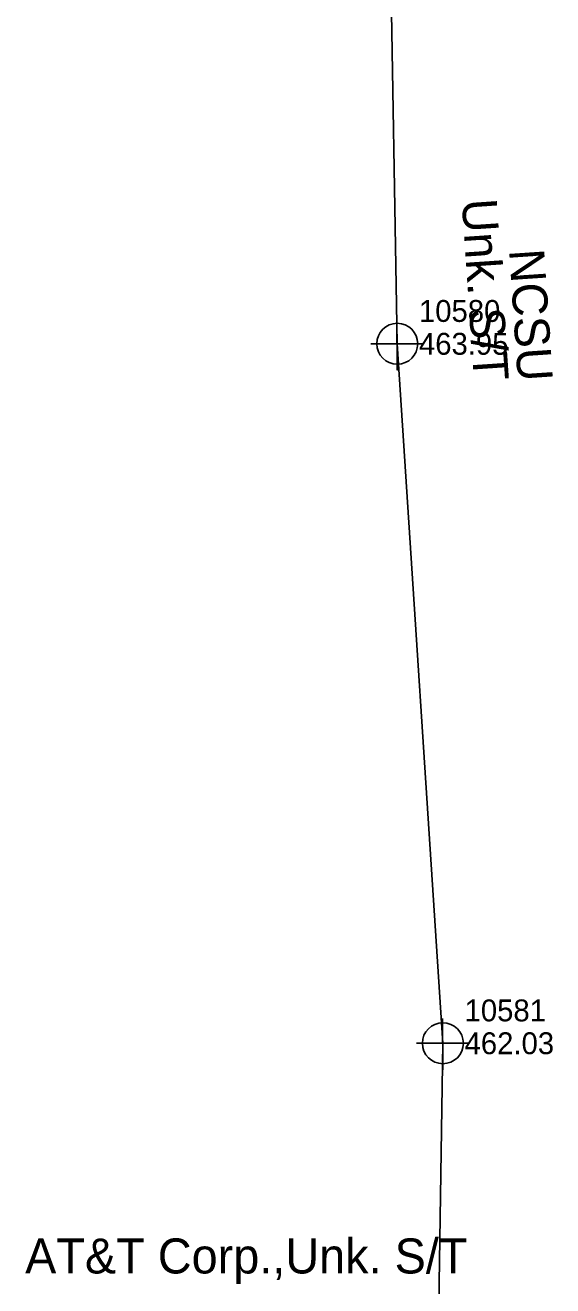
# Model space of a CAD drawing. Extents: x 2083698 to 2094313, y 743246 to 752873.
# Drawn here: x 2088906.7 to 2088967, y 744424 to 744568 of the extents above; entities that cross this region are included whole.
import ezdxf

# ---------------------------------------------------------------- set-up
doc = ezdxf.new("R2010")
doc.units = 0
for name, color, linetype in [('Exist Right of Way Line Leader', 7, 'Continuous'), ('Exist Right of Way Line Text', 7, 'Continuous'), ('Exist Utilities Telephone UG Conduit SUE LOS B', 7, 'Continuous'), ('Exist Utilities Telephone UG Conduit SUE LOS B Text', 7, 'Continuous'), ('Exist Utilities Telephone UG Conduit SUE LOS C Text', 7, 'Continuous'), ('Scratch_Level_2', 7, 'Continuous')]:
    doc.layers.add(name, color=color, linetype=linetype)

msp = doc.modelspace()

# ---------------------------------------------------------------- linework, layer by layer
at = {"layer": 'Exist Right of Way Line Text'}
for points in [[(2088949.16, 744534.38), (2088949.2, 744528.56), (2088949.18, 744531.56), (2088952.2, 744531.56), (2088946.2, 744531.56)], [(2088954.37, 744454.48), (2088954.41, 744448.66), (2088954.39, 744451.66), (2088957.41, 744451.66), (2088951.41, 744451.66)]]:
    msp.add_lwpolyline(points, dxfattribs=at)
for centre in [(2088949.2, 744531.56), (2088954.41, 744451.66)]:
    msp.add_circle(centre, 2.34, dxfattribs=at)
at = {"layer": 'Exist Utilities Telephone UG Conduit SUE LOS B'}
msp.add_lwpolyline([(2088935.74, 744764.1), (2088934.52, 744755.63), (2088934.8, 744737.13), (2088936.38, 744715.75), (2088939.38, 744689.14), (2088940.09, 744679.25), (2088942.38, 744644.84), (2088943.8, 744604.78), (2088948.38, 744578.34), (2088949.18, 744531.56), (2088954.39, 744451.66), (2088953.51, 744391.9), (2088955.51, 744361.96), (2088955.09, 744349.03), (2088964.56, 744321.28)], dxfattribs=at)

# ---------------------------------------------------------------- texts
at = {"layer": 'Exist Right of Way Line Leader'}
for s, p in [('10580', (2088951.68, 744534.06)), ('10581', (2088956.89, 744454.16))]:
    msp.add_text(s, height=2.5, dxfattribs=at).set_placement(p)
at = {"layer": 'Exist Utilities Telephone UG Conduit SUE LOS B Text'}
msp.add_text('AT&T Corp.,Unk. S/T', height=4, dxfattribs=at).set_placement((2088906.69, 744425.36))
at = {"layer": 'Exist Utilities Telephone UG Conduit SUE LOS C Text'}
for s, p in [('Unk. S/T', (2088956.56, 744548)), ('NCSU ', (2088961.97, 744542.27))]:
    msp.add_text(s, height=4, rotation=273.8705, dxfattribs=at).set_placement(p)
at = {"layer": 'Scratch_Level_2'}
for s, p in [('463.95', (2088951.68, 744530.31)), ('462.03', (2088956.89, 744450.41))]:
    msp.add_text(s, height=2.5, dxfattribs=at).set_placement(p)

doc.saveas('drawing.dxf')
